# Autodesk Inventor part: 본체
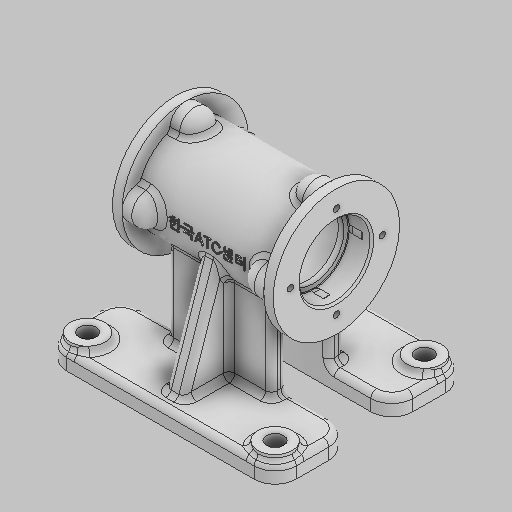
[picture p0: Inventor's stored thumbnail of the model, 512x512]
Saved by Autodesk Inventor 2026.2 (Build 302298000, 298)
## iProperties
Created: 2026-06
Part Number: 본체
Material: 일반
Document SubType Name: Modeling
Designer: sec7
Density: 1 g/cm^3
Appearance: 기본값
Author: sec7
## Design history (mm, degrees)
sketch "스케치1"
  geometry: L1 (-42, 0)-(42, 0); L2 (-42, 0)-(-42, 33); L3 (-42, 33)-(-37, 33); L4 (-37, 33)-(-37, 25); L5 (-37, 25)-(37, 25); L6 (37, 25)-(37, 33); L7 (37, 33)-(42, 33); L8 (42, 33)-(42, 0); L9 (-42, 18.5)-(-30.3, 18.5); L10 (-30, 18.2)-(-30, 0); L11 (42, 18.5)-(30.3, 18.5); L12 (30, 18.2)-(30, 0); L13 (-27, 0)-(-27, 20); L14 (-27, 20)-(27, 20); L15 (27, 20)-(27, 0); L16 (-30, 16)-(-27, 16); L17 (27, 16)-(30, 16); L18 (-37, 31.811)-(-32, 31.811); L19 (-37, 25)-(-24.089, 25); L20 (-37, 31.811)-(-37, 25); A1 r 0.3 centre (-30.3, 18.2) between (-30, 18.2) and (-30.3, 18.5); A2 r 0.3 centre (30.3, 18.2) between (30.3, 18.5) and (30, 18.2); A3 r 8 centre (-32, 23.811) between (-24.089, 25) and (-32, 31.811); 6 further points
  constraints: 40 end point, 18 point on line, 11 perpendicular, 6 point on circle, 5 tangent, 4 horizontal, 3 centre point, 3 midpoint, 2 collinear, 2 vertical, 1 coincident, 1 equal radius, 1 vertical alignment
  dimensions: "d0" = 84 distance of L1.start L1.end; "d1" = 66 diameter of L3 L1; "d2" = 50 diameter of L5 L1; "d3" = 5 distance between parallel lines of L2 L4; "d4" = 5 distance between parallel lines of L6 L8; "d5" = 12 distance between parallel lines of L10 L2; "d6" = 12 distance between parallel lines of L12 L8; "d7" = 40 diameter of L14 L1; "d8" = 66 diameter of L7 L1; "d9" = 37 diameter of L9 L1; "d10" = 37 diameter of L11 L1; "d11" = 32 diameter of L17 L1; "d12" = 54 distance of L13.end L14.end; "d14" = 0.3 radius of A1; "d123" = 8 radius of A3; "d124" = 10 distance from line of L18.end L2; "d129" = 1.1894 distance between parallel lines of L7 L18
revolve "회전1" stored, may be unused: angle "d13" = 360 deg
node "작업 평면4"
sketch "스케치2"
  geometry: L1 (60, 50)-(-60, 50); L2 (-60, 50)-(-60, 11); L3 (-60, 11)-(60, 11); L4 (60, 11)-(60, 50); L5 (60, -11)-(-60, -11); L6 (-60, -11)-(-60, -50); L7 (-60, -50)-(60, -50); L8 (60, -50)-(60, -11); 3 further points
  constraints: 16 end point, 4 parallel, 2 horizontal, 2 midpoint, 2 perpendicular, 2 point on line, 1 vertical alignment
  dimensions: "d18" = 39 distance of L7.end L5.start; "d19" = 39 distance of L3.end L1.start; "d21" = 50 distance from line of L1 point (0, 0); "d22" = 50 distance from line of L7 point (0, 0); "d23" = 60 distance from line of L8 point (0, -50)
extrude "돌출1" join sketch "스케치2" distance "d24" = 9; taper "d25" = 0 deg
sketch "스케치3"
  geometry: L1 (60, -11)-(-60, -11) reference; L2 (-27, -11)-(27, -11); L3 (27, -11)-(27, -19); L4 (27, -19)-(-27, -19); L5 (-27, -19)-(-27, -11); 4 further points
  constraints: 8 end point, 2 midpoint, 2 parallel, 1 horizontal, 1 perpendicular, 1 point on line, 1 vertical alignment
  dimensions: "d26" = 54 distance of L3.end L4.end; "d27" = 8 distance between parallel lines of L4 L1
extrude "돌출2" join sketch "스케치3" stored distance "d28" = 9; taper "d29" = 0 deg
sketch "스케치4"
  geometry: L1 (-60, 11)-(60, 11) reference; L2 (-27, 11)-(27, 11); L3 (27, 11)-(27, 19); L4 (27, 19)-(-27, 19); L5 (-27, 19)-(-27, 11); 4 further points
  constraints: 8 end point, 2 midpoint, 2 parallel, 1 horizontal, 1 perpendicular, 1 point on line, 1 vertical alignment
  dimensions: "d30" = 54 distance of L3.end L4.end; "d31" = 8 distance of L2.end L3.end
extrude "돌출3" join sketch "스케치4" stored distance "d32" = 10; taper "d33" = 0 deg
node "작업 평면5"
sketch "스케치5"
  geometry: L1 (-6.346, 24.181)-(-61, 43); L2 (-61, 11)-(-61, 50) reference; L3 (-70, 50)-(-61, 50) reference; L4 (-61, 19)-(-16.248, 19) reference; L5 (-6.346, -24.181)-(-61, -43); L6 (-61, -50)-(-61, -11) reference; L7 (-70, -50)-(-61, -50) reference; L8 (-61, -19)-(-16.248, -19) reference; A1 r 25 centre (0, 0) between (-6.346, 24.181) and (-16.248, 19) reference; 1 further point
  constraints: 4 end point, 2 point on circle, 2 point on line
  dimensions: "d36" = 7 distance from line of L1.end L3; "d37" = 19 deg angle of L4 L1; "d38" = 7 distance from line of L5.end L7; "d39" = 19 deg angle of L8 L5
extrude "돌출4" join sketch "스케치5" stored distance "d40" = 10; taper "d41" = 0 deg
sketch "스케치6"
  geometry: A1 r 24 centre (0, 0) between (0, 24) and (-24, 0); 3 further points
  constraints: 4 point on circle, 1 centre point, 1 coincident
  dimensions: "d42" = 48 diameter of A1
hole "구멍1" sketch "스케치6" at (0, 24), (-24, 0), (0, -24), (24, 0) diameter "d43" = 3.242; stored, may be unused: countersink angle "d47" = 90 deg, drill point angle "d49" = 118 deg; dims "d44" = 8, "d45" = 4, "d46" = 2, "d48" = 10
sketch "스케치8"
  geometry: L1 (0, 0)-(0, 25); C1 r 18.5 at (0, 0) reference; C2 r 8 at (0, 25); C3 r 33 at (0, 0) reference; C4 r 8 at (-25, 0); C5 r 8 at (0, -25); C6 r 8 at (25, 0); C7 r 25 at (0, 0); 17 further points
  constraints: 5 centre point, 2 coincident, 2 end point, 1 tangent, 1 vertical, 9 other
  dimensions: "d64" = 8 radius of C2; "d74" = 360 deg dimension on point (0, 0) C2.centre (derived); "d112" = 50 diameter of C7
  node "스케치 - 원형 패턴3" dims "d74" = 360 deg (derived)
node "작업 평면9"
sketch "스케치10"
  geometry: L1 (42, 33)-(42, -33) reference; L2 (-60, -50)-(60, -50) reference; L3 (60, 50)-(-60, 50) reference; C1 r 9 at (49, 39); C2 r 9 at (49, -39); 4 further points
  constraints: 3 midpoint, 2 centre point
  dimensions: "d84" = 18 diameter of C1; "d85" = 39 vertical distance of C1.centre point (42, 0); "d86" = 18 diameter of C2; "d87" = 39 vertical distance of C2.centre point (42, 0); "d88" = 49 horizontal distance of point (0, -50) C2.centre; "d89" = 49 horizontal distance of point (0, 50) C1.centre (= d88)
extrude "돌출7" join sketch "스케치10" distance "d90" = 3; taper "d91" = 0 deg
sketch "스케치11"
  geometry: C1 r 9 at (0, 0) reference; 2 further points
  constraints: 1 coincident
hole "구멍3" sketch "스케치11" at (0, 0) diameter "d92" = 9; stored, may be unused: countersink angle "d96" = 90 deg, drill point angle "d98" = 0 deg; dims "d93" = 6, "d94" = 4, "d95" = 2, "d97" = 12
sketch "스케치12"
  geometry: C1 r 9 at (0, 0) reference; 2 further points
  constraints: 1 coincident
hole "구멍4" sketch "스케치12" at (0, 0) diameter "d99" = 9; stored, may be unused: countersink angle "d103" = 90 deg, drill point angle "d105" = 0 deg; dims "d100" = 6, "d101" = 4, "d102" = 2, "d104" = 12
chamfer "모따기1" distance "d106" = 1; stored, may be unused: second distance "d107" = 2, angle "d108" = 45 deg
chamfer "모따기2" distance "d109" = 1; stored, may be unused: second distance "d110" = 2, angle "d111" = 45 deg
extrude "돌출8" join sketch "스케치8" distance "d113" = 13; taper "d114" = 0 deg
node "작업 평면10"
sketch "스케치13"
  geometry: L1 (-10.365, 3.002)-(10.365, 3.002); L2 (10.365, 3.002)-(10.365, -3.002); L3 (10.365, -3.002)-(-10.365, -3.002); L4 (-10.365, -3.002)-(-10.365, 3.002); L5 (-60, -70)-(60, -70) reference; 4 further points
  constraints: 3 midpoint, 1 vertical alignment, 2 other
  dimensions: "d120" = 70 distance from line of L5 point (10.365, 0)
feature "엠보싱1" sketch "스케치13" dims "d0" = 84, "d1" = 66, "d2" = 50, "d3" = 5, "d4" = 5, "d5" = 12, "d6" = 12, "d7" = 40, "d8" = 66, "d9" = 37, "d10" = 37, "d11" = 32, "d12" = 54, "d14" = 0.3, "d121" = 0.5, "d122" = 0, "d123" = 8, "d124" = 10, "d129" = 1.1894
revolve "회전3" stored, may be unused: angle "d125" = 90 deg
fillet "모깎기5" dims "d130" = 11
node "작업 평면12"
sketch "스케치15"
  geometry: L1 (-27, -19)-(-27, -11) reference; L2 (-49, 11)-(49, 11) reference; L3 (49, -11)-(-49, -11) reference; L4 (-27, 11)-(26.915, 11); L5 (26.915, -11)-(-27, -11); L6 (-5, 11)-(-5, -11); L7 (5, 11)-(5, -11); 5 further points
  constraints: 8 end point, 7 point on line, 2 collinear, 2 perpendicular
  dimensions: "d137" = 5 distance from line of L6 point (0, 0); "d138" = 5 distance from line of point (0, 0) L7
extrude "돌출9" join sketch "스케치15" stored distance "d135" = 13; taper "d136" = 0 deg
fillet "모깎기11" dims "d144" = 3, "d145" = 3
fillet "모깎기12" dims "d146" = 3
fillet "모깎기13" dims "d147" = 3
fillet "모깎기14" dims "d148" = 3
fillet "모깎기15" dims "d149" = 3
fillet "모깎기16" dims "d150" = 8
fillet "모깎기17" dims "d151" = 3
fillet "모깎기6" dims "d139" = 3
fillet "모깎기7" dims "d140" = 3
fillet "모깎기8" dims "d141" = 3
fillet "모깎기9" dims "d142" = 3
node "솔리드1"
mirror "미러1"
mirror "미러4"
mirror "미러5"
pattern_circular "원형 패턴1" dims angle "d127" = 360 deg
mirror "미러6"
feature "A9D066F2-1C7D-4E18-AEED-F7BC21143FA4" dims "d92" = 9, "d93" = 6, "d94" = 4, "d95" = 2, "d96" = 90 deg, "d97" = 12, "d98" = 0
other parameters: "d35" = 0, "d83" = -61, "d119" = 38.25
